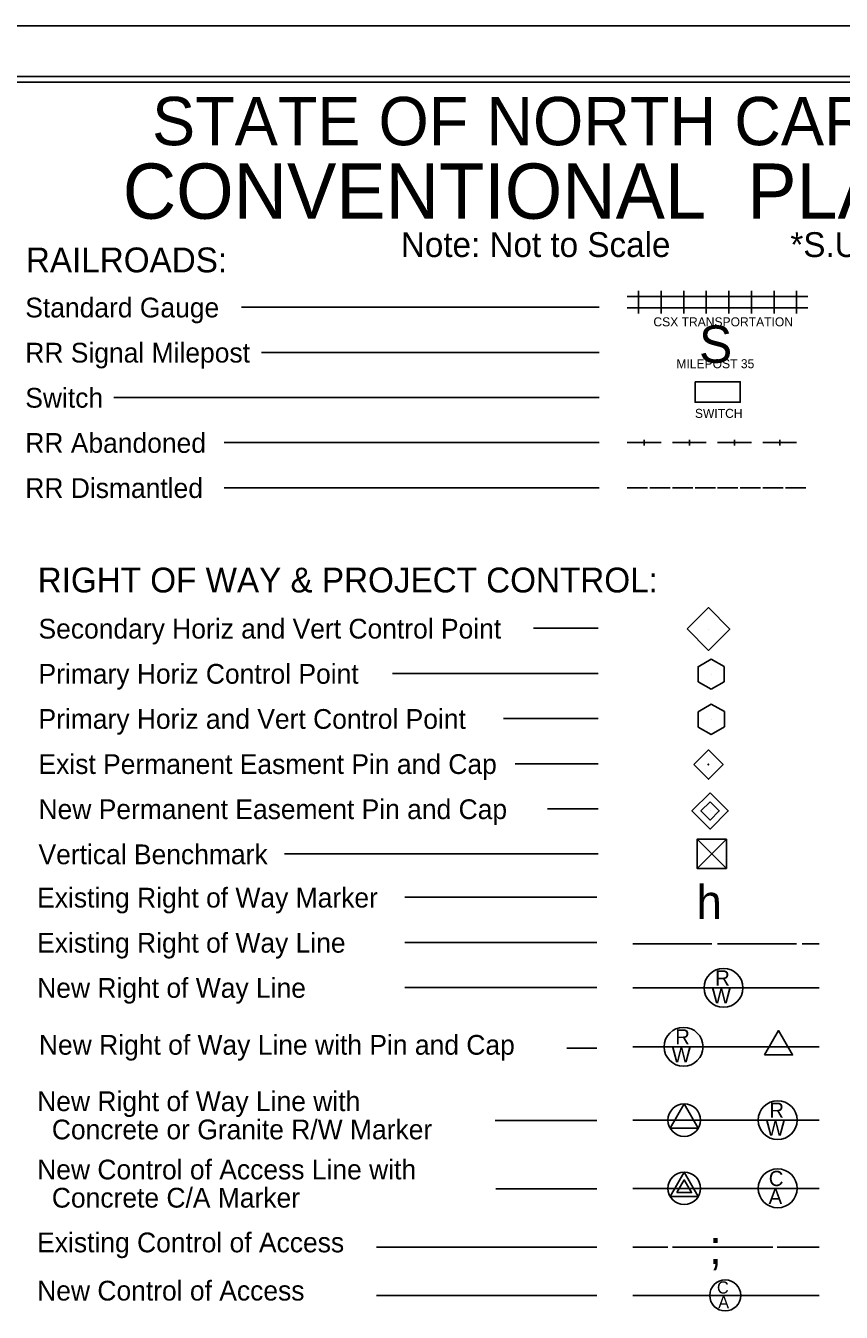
# Model space of a CAD drawing. Extents: x 1729964 to 1731648, y 539487 to 540587.
# Drawn here: x 1730526 to 1730887, y 540017 to 540587 of the extents above; entities that cross this region are included whole.
import ezdxf

# ---------------------------------------------------------------- set-up
doc = ezdxf.new("R2010")
doc.units = 0
for name, color, linetype in [('Prop ROW Permanent Easement CELL', 7, 'Continuous'), ('Sheet Cutting Line CELL', 7, 'Continuous'), ('Sheet Plot Border Inside CELL', 7, 'Continuous'), ('Sheet Plot Border Outside CELL', 7, 'Continuous'), ('Sheet Symbology CELL', 7, 'Continuous')]:
    doc.layers.add(name, color=color, linetype=linetype)

msp = doc.modelspace()

# ---------------------------------------------------------------- linework, layer by layer
at = {"layer": 'Prop ROW Permanent Easement CELL'}
msp.add_line((1730829.12, 540239.44), (1730829.12, 540239.44), dxfattribs=at)
for points in [[(1730829.12, 540247.49), (1730837.18, 540239.44), (1730829.12, 540231.39), (1730821.07, 540239.44)], [(1730829.12, 540243.46), (1730833.15, 540239.44), (1730829.12, 540235.41), (1730825.1, 540239.44)]]:
    msp.add_lwpolyline(points, close=True, dxfattribs=at)
at = {"layer": 'Sheet Cutting Line CELL'}
msp.add_line((1731648.46, 540587.38), (1729964.46, 540587.38), dxfattribs=at)
at = {"layer": 'Sheet Plot Border Inside CELL'}
msp.add_lwpolyline([(1729977.46, 539509.83), (1731643.96, 539509.83), (1731643.96, 540564.93), (1729977.46, 540564.93)], close=True, dxfattribs=at)
at = {"layer": 'Sheet Plot Border Outside CELL'}
for p, q in [((1730828.33, 540320.03), (1730828.33, 540320.03)), ((1730829.64, 540300.02), (1730829.64, 540300.02)), ((1730829.64, 540280.02), (1730829.64, 540280.02)), ((1730828.36, 540259.99), (1730828.36, 540259.99)), ((1730829.89, 540220.41), (1730829.89, 540220.41))]:
    msp.add_line(p, q, dxfattribs=at)
for points in [[(1729964.46, 539487.38), (1731648.46, 539487.38), (1731648.46, 540587.38), (1729964.46, 540587.38)], [(1730818.92, 540320.06), (1730828.38, 540329.52), (1730837.85, 540320.04), (1730828.4, 540310.59)], [(1730823.81, 540283.4), (1730829.67, 540286.67), (1730835.53, 540283.44), (1730835.44, 540276.72), (1730829.58, 540273.32), (1730823.81, 540276.59)], [(1730821.87, 540259.99), (1730828.36, 540266.48), (1730834.86, 540259.99), (1730828.36, 540253.49)], [(1730823.39, 540226.89), (1730836.36, 540226.89), (1730836.36, 540213.92), (1730823.39, 540213.92)]]:
    msp.add_lwpolyline(points, close=True, dxfattribs=at)
for points in [[(1730829.64, 540293.37), (1730823.84, 540296.66), (1730823.84, 540303.32), (1730829.64, 540306.68), (1730835.43, 540303.39), (1730835.43, 540296.66), (1730829.64, 540293.37)], [(1730836.36, 540226.89), (1730823.39, 540213.92), (1730829.87, 540220.4), (1730836.36, 540213.92), (1730823.39, 540226.89)], [(1730829.87, 540220.4), (1730836.36, 540226.89), (1730823.39, 540226.89), (1730829.87, 540220.4)], [(1730829.87, 540220.4), (1730823.39, 540213.92), (1730836.36, 540213.92), (1730829.87, 540220.4)]]:
    msp.add_lwpolyline(points, dxfattribs=at)
msp.add_circle((1730828.36, 540259.99), 0.126, dxfattribs=at)
at = {"layer": 'Sheet Symbology CELL'}
for p, q in [((1730792.46, 540467.41), (1730802.46, 540467.41)), ((1730797.46, 540459.91), (1730797.46, 540469.91)), ((1730802.46, 540467.41), (1730812.46, 540467.41)), ((1730807.46, 540459.91), (1730807.46, 540469.91)), ((1730812.46, 540467.41), (1730822.46, 540467.41)), ((1730817.46, 540459.91), (1730817.46, 540469.91)), ((1730822.46, 540467.41), (1730832.46, 540467.41)), ((1730827.46, 540459.91), (1730827.46, 540469.91)), ((1730832.46, 540467.41), (1730842.46, 540467.41)), ((1730837.46, 540459.91), (1730837.46, 540469.91)), ((1730842.46, 540467.41), (1730852.46, 540467.41)), ((1730847.46, 540459.91), (1730847.46, 540469.91)), ((1730852.46, 540467.41), (1730862.46, 540467.41)), ((1730857.46, 540459.91), (1730857.46, 540469.91)), ((1730862.46, 540467.41), (1730872.46, 540467.41)), ((1730867.46, 540459.91), (1730867.46, 540469.91)), ((1730780.07, 540462.65), (1730621.66, 540462.65)), ((1730792.46, 540462.41), (1730802.46, 540462.41)), ((1730802.46, 540462.41), (1730812.46, 540462.41)), ((1730812.46, 540462.41), (1730822.46, 540462.41)), ((1730822.46, 540462.41), (1730832.46, 540462.41)), ((1730832.46, 540462.41), (1730842.46, 540462.41)), ((1730842.46, 540462.41), (1730852.46, 540462.41)), ((1730852.46, 540462.41), (1730862.46, 540462.41)), ((1730862.46, 540462.41), (1730872.46, 540462.41)), ((1730780.07, 540442.65), (1730630.52, 540442.65)), ((1730780.07, 540422.65), (1730565.16, 540422.65)), ((1730799.96, 540403.9), (1730799.96, 540401.4)), ((1730819.96, 540403.9), (1730819.96, 540401.4)), ((1730839.96, 540403.9), (1730839.96, 540401.4)), ((1730859.96, 540403.9), (1730859.96, 540401.4)), ((1730780.07, 540402.65), (1730613.91, 540402.65)), ((1730792.46, 540402.65), (1730807.46, 540402.65)), ((1730812.46, 540402.65), (1730827.46, 540402.65)), ((1730832.46, 540402.65), (1730847.46, 540402.65)), ((1730852.46, 540402.65), (1730867.46, 540402.65)), ((1730780.07, 540382.65), (1730613.91, 540382.65)), ((1730780.07, 540382.65), (1730613.91, 540382.65)), ((1730792.46, 540382.65), (1730801.46, 540382.65)), ((1730802.46, 540382.65), (1730811.46, 540382.65)), ((1730812.46, 540382.65), (1730821.46, 540382.65)), ((1730822.46, 540382.65), (1730831.46, 540382.65)), ((1730832.46, 540382.65), (1730841.46, 540382.65)), ((1730842.46, 540382.65), (1730851.46, 540382.65)), ((1730852.46, 540382.65), (1730861.46, 540382.65)), ((1730862.46, 540382.65), (1730871.46, 540382.65)), ((1730779.52, 540320.36), (1730750.97, 540320.36)), ((1730779.52, 540300.36), (1730688.49, 540300.36)), ((1730779.52, 540280.36), (1730737.6, 540280.36)), ((1730779.52, 540260.36), (1730742.82, 540260.36)), ((1730779.52, 540240.36), (1730757.16, 540240.36)), ((1730779.52, 540220.36), (1730640.68, 540220.36)), ((1730778.93, 540201.17), (1730693.99, 540201.17)), ((1730778.93, 540181.17), (1730693.99, 540181.17)), ((1730794.96, 540180.6), (1730829.96, 540180.6)), ((1730832.46, 540180.6), (1730867.46, 540180.6)), ((1730869.96, 540180.6), (1730877.46, 540180.6)), ((1730778.93, 540161.17), (1730693.99, 540161.17)), ((1730794.96, 540161.05), (1730877.46, 540161.05)), ((1730778.93, 540134.32), (1730765.69, 540134.32)), ((1730794.96, 540134.92), (1730877.46, 540134.92)), ((1730859.41, 540134.92), (1730859.41, 540134.92)), ((1730778.93, 540102.29), (1730733.94, 540102.29)), ((1730794.96, 540102.42), (1730877.46, 540102.42)), ((1730817.66, 540102.42), (1730817.66, 540102.42)), ((1730778.93, 540072.04), (1730734.32, 540072.04)), ((1730794.96, 540072.18), (1730877.46, 540072.18)), ((1730817.66, 540072.18), (1730817.66, 540072.18)), ((1730778.93, 540046.1), (1730681.38, 540046.1)), ((1730794.96, 540046.1), (1730810.42, 540046.1)), ((1730812.42, 540046.1), (1730856.84, 540046.1)), ((1730858.84, 540046.1), (1730877.46, 540046.1)), ((1730778.93, 540024.75), (1730681.38, 540024.75)), ((1730794.96, 540024.75), (1730877.46, 540024.75))]:
    msp.add_line(p, q, dxfattribs=at)
for points in [[(1731631.46, 540562.38), (1730131.46, 540562.38), (1730131.46, 539513.4), (1731631.46, 539513.4)], [(1730822.46, 540429.61), (1730842.46, 540429.61), (1730842.46, 540420.51), (1730822.46, 540420.51)], [(1730853.16, 540131.32), (1730859.41, 540142.12), (1730865.66, 540131.32)], [(1730811.41, 540098.82), (1730817.66, 540109.62), (1730823.91, 540098.82)], [(1730811.41, 540068.58), (1730823.91, 540068.58), (1730817.66, 540079.38)], [(1730814.39, 540070.3), (1730817.66, 540075.94), (1730820.93, 540070.3)]]:
    msp.add_lwpolyline(points, close=True, dxfattribs=at)
for centre, radius in [((1730835.08, 540161.05), 8.61), ((1730817.38, 540134.92), 8.61), ((1730817.66, 540102.42), 7.2), ((1730859.06, 540102.42), 8.61), ((1730817.66, 540072.18), 7.2), ((1730859.06, 540072.18), 8.61), ((1730835.84, 540024.75), 6.89)]:
    msp.add_circle(centre, radius, dxfattribs=at)

# ---------------------------------------------------------------- texts
for s, height, p in [('STATE OF NORTH CAROLINA, DIVISION OF HIGHWAYS', 21.419, (1730582.03, 540534.42)), ('CONVENTIONAL  PLAN SHEET SYMBOLS', 24.4803, (1730569.07, 540501.85)), ('RAILROADS:', 11, (1730526.18, 540478.1)), ('Standard Gauge', 8.75, (1730525.91, 540458.12)), ('S', 16.5, (1730824.23, 540438.02)), ('RR Signal Milepost', 8.75, (1730525.91, 540438.12)), ('Switch', 8.75, (1730525.91, 540418.12)), ('RR Abandoned', 8.75, (1730525.91, 540398.12)), ('RR Dismantled', 8.75, (1730525.91, 540378.12)), ('RIGHT OF WAY & PROJECT CONTROL:', 11, (1730531.4, 540336.25)), ('Secondary Horiz and Vert Control Point', 8.75, (1730531.77, 540315.81)), ('Primary Horiz Control Point', 8.75, (1730531.77, 540295.81)), ('Primary Horiz and Vert Control Point', 8.75, (1730531.77, 540275.81)), ('Exist Permanent Easment Pin and Cap', 8.75, (1730531.77, 540255.81)), ('New Permanent Easement Pin and Cap', 8.75, (1730531.77, 540235.81)), ('Vertical Benchmark', 8.75, (1730531.77, 540215.81)), ('Existing Right of Way Marker', 8.75, (1730531.18, 540196.62)), ('h', 15, (1730823.15, 540191.6)), ('Existing Right of Way Line', 8.75, (1730531.18, 540176.62)), ('New Right of Way Line', 8.75, (1730531.18, 540156.62)), ('R', 6.75, (1730831.37, 540162.06)), ('W', 6.75, (1730829.84, 540154.11)), ('R', 6.75, (1730813.67, 540135.94)), ('New Right of Way Line with Pin and Cap', 8.75, (1730531.94, 540131.4)), ('W', 6.75, (1730812.14, 540127.99)), ('New Right of Way Line with', 8.75, (1730531.18, 540106.4)), ('R', 6.75, (1730855.35, 540103.44)), ('  Concrete or Granite R/W Marker', 8.75, (1730531.18, 540093.9)), ('W', 6.75, (1730853.81, 540095.49)), ('New Control of Access Line with', 8.75, (1730531.18, 540076.15)), ('C', 6.75, (1730855.1, 540073.19)), ('  Concrete C/A Marker', 8.75, (1730531.18, 540063.65)), ('A', 6.75, (1730855.03, 540065.24)), ('Existing Control of Access', 8.75, (1730531.18, 540043.84)), (';', 15, (1730828.71, 540038.6)), ('New Control of Access', 8.75, (1730531.18, 540022.48)), ('C', 5.4, (1730832.17, 540025.56)), ('A', 5.4, (1730832.71, 540019.07))]:
    msp.add_text(s, height=height, dxfattribs=at).set_placement(p)
for s, height, p in [('Note: Not to Scale', 11, (1730692.21, 540484.89)), ('*S.U.E. = Subsurface Utility Engineering', 11, (1730864.68, 540484.89)), ('CSX TRANSPORTATION', 4, (1730804.03, 540454.17)), ('MILEPOST 35', 4, (1730814.21, 540435.6)), ('SWITCH', 4, (1730822.41, 540413.6))]:
    msp.add_text(s, height=height, rotation=360, dxfattribs=at).set_placement(p)

doc.saveas('drawing.dxf')
